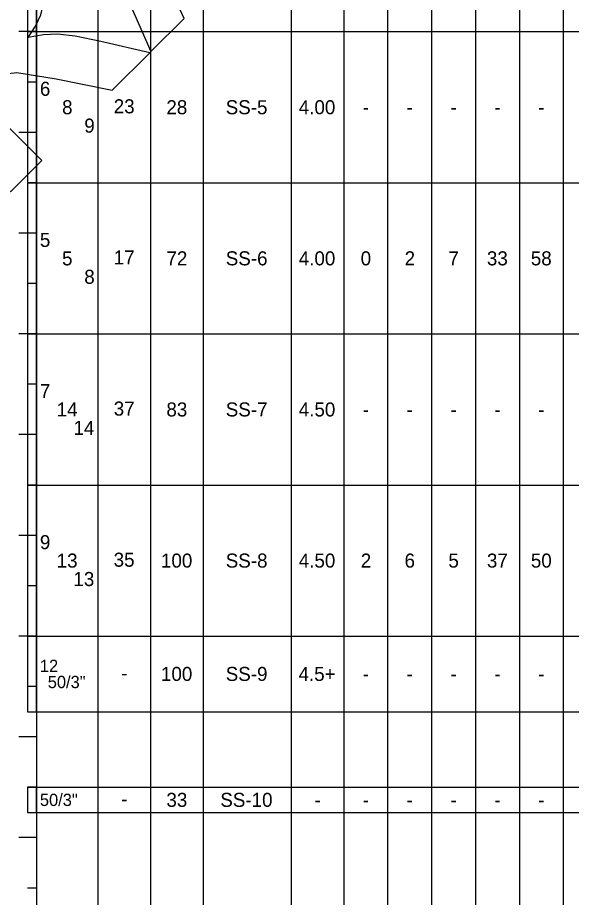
# Model space of a CAD drawing. Extents: x -0.01 to 0.83, y -0.63 to 1.27.
# Drawn here: x 0.4036 to 0.6664, y 0.45 to 0.8677 of the extents above; entities that cross this region are included whole.
import ezdxf

# ---------------------------------------------------------------- set-up
doc = ezdxf.new("R2010")
doc.units = 0

# ---------------------------------------------------------------- blocks, each defined once
blk = doc.blocks.new('DGRFC!DRAFT - ARIAL')
for points in [[(0, 0), (0.03155, 0), (0.03997, 0.00043), (0.04651, 0.00179), (0.05315, 0.00468), (0.05825, 0.00842), (0.06344, 0.01497), (0.06726, 0.02313), (0.06913, 0.03129), (0.06981, 0.0409), (0.06913, 0.05162), (0.06709, 0.06054), (0.06369, 0.06794), (0.05901, 0.07406), (0.05638, 0.07662), (0.05332, 0.07874), (0.05008, 0.08044), (0.0466, 0.08172), (0.03988, 0.08291), (0.03078, 0.08333), (0, 0.08333)], [(0.0841, 0), (0.10094, 0), (0.10094, 0.03478), (0.10434, 0.03478), (0.10935, 0.03452), (0.11275, 0.03376), (0.11539, 0.0324), (0.11786, 0.03036), (0.1267, 0.01811), (0.13878, 0), (0.15893, 0), (0.14872, 0.01616), (0.14337, 0.02449), (0.1392, 0.02976), (0.1352, 0.03333), (0.13027, 0.03673), (0.13537, 0.03776), (0.1398, 0.03946), (0.14354, 0.04167), (0.14668, 0.04439), (0.14906, 0.0477), (0.15085, 0.05136), (0.15187, 0.05544), (0.15221, 0.05986), (0.15128, 0.06692), (0.14847, 0.07313), (0.1466, 0.07577), (0.1443, 0.07798), (0.14175, 0.07968), (0.13878, 0.08104), (0.13537, 0.08206), (0.13095, 0.08274), (0.11947, 0.08333), (0.0841, 0.08333)], [(0.15952, 0), (0.1773, 0), (0.18427, 0.01896), (0.21752, 0.01896), (0.22474, 0), (0.24311, 0), (0.20978, 0.08333), (0.19192, 0.08333)], [(0.25204, 0), (0.26888, 0), (0.26888, 0.03546), (0.30349, 0.03546), (0.30349, 0.04949), (0.26888, 0.04949), (0.26888, 0.06922), (0.30901, 0.06922), (0.30901, 0.08333), (0.25204, 0.08333)], [(0.34167, 0), (0.3585, 0), (0.3585, 0.06922), (0.38308, 0.06922), (0.38308, 0.08333), (0.31701, 0.08333), (0.31701, 0.06922), (0.34167, 0.06922)], [(0.01684, 0.01412), (0.02942, 0.01412), (0.03954, 0.01488), (0.04328, 0.01616), (0.04634, 0.01828), (0.04881, 0.02151), (0.05077, 0.02636), (0.05213, 0.03291), (0.05247, 0.04167), (0.05213, 0.05017), (0.05085, 0.05646), (0.04872, 0.06105), (0.046, 0.06446), (0.04243, 0.06692), (0.03818, 0.06845), (0.03299, 0.06905), (0.0244, 0.06922), (0.01684, 0.06922)], [(0.10094, 0.04804), (0.11335, 0.04804), (0.12313, 0.0483), (0.1284, 0.04906), (0.13112, 0.05051), (0.13308, 0.05264), (0.13444, 0.05544), (0.13486, 0.05884), (0.13427, 0.06267), (0.13257, 0.06565), (0.12985, 0.06777), (0.12628, 0.06896), (0.11403, 0.06922), (0.10094, 0.06922)], [(0.18937, 0.03299), (0.21216, 0.03299), (0.20068, 0.06386)]]:
    blk.add_lwpolyline(points, close=True)

msp = doc.modelspace()

# ---------------------------------------------------------------- linework, layer by layer
for points in [[(0.4125, 1.22083), (0.4125, -0.62183)], [(0.4125, 1.22083), (0.4125, -0.62183)], [(0.44167, 1.22083), (0.44167, -0.62183)], [(0.46667, 1.22083), (0.46667, -0.62183)], [(0.49167, 1.22083), (0.49167, -0.62183)], [(0.53333, 1.22083), (0.53333, -0.62183)], [(0.55833, 1.22083), (0.55833, -0.62183)], [(0.6625, 1.22083), (0.6625, -0.62183)], [(0.57917, 1.20833), (0.57917, -0.62183)], [(0.6, 1.20833), (0.6, -0.62183)], [(0.62083, 1.20833), (0.62083, -0.62183)], [(0.64167, 1.20833), (0.64167, -0.62183)], [(0.40833, 0.93275), (0.40833, 0.861)], [(0.4125, 0.861), (0.40417, 0.861)], [(0.40833, 0.861), (0.4125, 0.861)], [(0.40833, 0.861), (0.40833, 0.78925)], [(0.40833, 0.861), (0.4125, 0.861)], [(0.4125, 0.861), (0.40833, 0.861)], [(0.4125, 0.861), (0.44167, 0.861)], [(0.44167, 0.861), (0.46667, 0.861)], [(0.46667, 0.861), (0.49167, 0.861)], [(0.49167, 0.861), (0.53333, 0.861)], [(0.53333, 0.861), (0.55833, 0.861)], [(0.55833, 0.861), (0.57917, 0.861)], [(0.57917, 0.861), (0.6, 0.861)], [(0.6, 0.861), (0.62083, 0.861)], [(0.62083, 0.861), (0.64167, 0.861)], [(0.64167, 0.861), (0.6625, 0.861)], [(0.6625, 0.861), (0.68333, 0.861)], [(0.4125, 0.83708), (0.40833, 0.83708)], [(0.4125, 0.81317), (0.40417, 0.81317)], [(0.4125, 0.81317), (0.40833, 0.81317)], [(0.40833, 0.78925), (0.4125, 0.78925)], [(0.40833, 0.78925), (0.40833, 0.7175)], [(0.40833, 0.78925), (0.4125, 0.78925)], [(0.4125, 0.78925), (0.40833, 0.78925)], [(0.4125, 0.78925), (0.44167, 0.78925)], [(0.44167, 0.78925), (0.46667, 0.78925)], [(0.46667, 0.78925), (0.49167, 0.78925)], [(0.49167, 0.78925), (0.53333, 0.78925)], [(0.53333, 0.78925), (0.55833, 0.78925)], [(0.55833, 0.78925), (0.57917, 0.78925)], [(0.57917, 0.78925), (0.6, 0.78925)], [(0.6, 0.78925), (0.62083, 0.78925)], [(0.62083, 0.78925), (0.64167, 0.78925)], [(0.64167, 0.78925), (0.6625, 0.78925)], [(0.6625, 0.78925), (0.68333, 0.78925)], [(0.4125, 0.76533), (0.40417, 0.76533)], [(0.4125, 0.76533), (0.40833, 0.76533)], [(0.4125, 0.74142), (0.40833, 0.74142)], [(0.4125, 0.7175), (0.40417, 0.7175)], [(0.40833, 0.7175), (0.4125, 0.7175)], [(0.40833, 0.7175), (0.40833, 0.64575)], [(0.40833, 0.7175), (0.4125, 0.7175)], [(0.4125, 0.7175), (0.40833, 0.7175)], [(0.4125, 0.7175), (0.44167, 0.7175)], [(0.44167, 0.7175), (0.46667, 0.7175)], [(0.46667, 0.7175), (0.49167, 0.7175)], [(0.49167, 0.7175), (0.53333, 0.7175)], [(0.53333, 0.7175), (0.55833, 0.7175)], [(0.55833, 0.7175), (0.57917, 0.7175)], [(0.57917, 0.7175), (0.6, 0.7175)], [(0.6, 0.7175), (0.62083, 0.7175)], [(0.62083, 0.7175), (0.64167, 0.7175)], [(0.64167, 0.7175), (0.6625, 0.7175)], [(0.6625, 0.7175), (0.68333, 0.7175)], [(0.4125, 0.69358), (0.40833, 0.69358)], [(0.4125, 0.66967), (0.40417, 0.66967)], [(0.4125, 0.66967), (0.40833, 0.66967)], [(0.40833, 0.64575), (0.4125, 0.64575)], [(0.40833, 0.64575), (0.40833, 0.574)], [(0.40833, 0.64575), (0.4125, 0.64575)], [(0.4125, 0.64575), (0.40833, 0.64575)], [(0.4125, 0.64575), (0.44167, 0.64575)], [(0.44167, 0.64575), (0.46667, 0.64575)], [(0.46667, 0.64575), (0.49167, 0.64575)], [(0.49167, 0.64575), (0.53333, 0.64575)], [(0.53333, 0.64575), (0.55833, 0.64575)], [(0.55833, 0.64575), (0.57917, 0.64575)], [(0.57917, 0.64575), (0.6, 0.64575)], [(0.6, 0.64575), (0.62083, 0.64575)], [(0.62083, 0.64575), (0.64167, 0.64575)], [(0.64167, 0.64575), (0.6625, 0.64575)], [(0.6625, 0.64575), (0.68333, 0.64575)], [(0.4125, 0.62183), (0.40417, 0.62183)], [(0.4125, 0.62183), (0.40833, 0.62183)], [(0.4125, 0.59792), (0.40833, 0.59792)], [(0.4125, 0.574), (0.40417, 0.574)], [(0.40833, 0.574), (0.4125, 0.574)], [(0.40833, 0.574), (0.40833, 0.53812)], [(0.40833, 0.574), (0.4125, 0.574)], [(0.4125, 0.574), (0.40833, 0.574)], [(0.4125, 0.574), (0.44167, 0.574)], [(0.44167, 0.574), (0.46667, 0.574)], [(0.46667, 0.574), (0.49167, 0.574)], [(0.49167, 0.574), (0.53333, 0.574)], [(0.53333, 0.574), (0.55833, 0.574)], [(0.55833, 0.574), (0.57917, 0.574)], [(0.57917, 0.574), (0.6, 0.574)], [(0.6, 0.574), (0.62083, 0.574)], [(0.62083, 0.574), (0.64167, 0.574)], [(0.64167, 0.574), (0.6625, 0.574)], [(0.6625, 0.574), (0.68333, 0.574)], [(0.4125, 0.55008), (0.40833, 0.55008)], [(0.40833, 0.53812), (0.4125, 0.53812)], [(0.4125, 0.53812), (0.44167, 0.53812)], [(0.44167, 0.53812), (0.46667, 0.53812)], [(0.46667, 0.53812), (0.49167, 0.53812)], [(0.49167, 0.53812), (0.53333, 0.53812)], [(0.53333, 0.53812), (0.55833, 0.53812)], [(0.55833, 0.53812), (0.57917, 0.53812)], [(0.57917, 0.53812), (0.6, 0.53812)], [(0.6, 0.53812), (0.62083, 0.53812)], [(0.62083, 0.53812), (0.64167, 0.53812)], [(0.64167, 0.53812), (0.6625, 0.53812)], [(0.6625, 0.53812), (0.68333, 0.53812)], [(0.4125, 0.52617), (0.40417, 0.52617)], [(0.4125, 0.52617), (0.40833, 0.52617)], [(0.40833, 0.50225), (0.40833, 0.49029)], [(0.40833, 0.50225), (0.4125, 0.50225)], [(0.4125, 0.50225), (0.40833, 0.50225)], [(0.4125, 0.50225), (0.44167, 0.50225)], [(0.44167, 0.50225), (0.46667, 0.50225)], [(0.46667, 0.50225), (0.49167, 0.50225)], [(0.49167, 0.50225), (0.53333, 0.50225)], [(0.53333, 0.50225), (0.55833, 0.50225)], [(0.55833, 0.50225), (0.57917, 0.50225)], [(0.57917, 0.50225), (0.6, 0.50225)], [(0.6, 0.50225), (0.62083, 0.50225)], [(0.62083, 0.50225), (0.64167, 0.50225)], [(0.64167, 0.50225), (0.6625, 0.50225)], [(0.6625, 0.50225), (0.68333, 0.50225)], [(0.40833, 0.49029), (0.4125, 0.49029)], [(0.4125, 0.49029), (0.44167, 0.49029)], [(0.44167, 0.49029), (0.46667, 0.49029)], [(0.46667, 0.49029), (0.49167, 0.49029)], [(0.49167, 0.49029), (0.53333, 0.49029)], [(0.53333, 0.49029), (0.55833, 0.49029)], [(0.55833, 0.49029), (0.57917, 0.49029)], [(0.57917, 0.49029), (0.6, 0.49029)], [(0.6, 0.49029), (0.62083, 0.49029)], [(0.62083, 0.49029), (0.64167, 0.49029)], [(0.64167, 0.49029), (0.6625, 0.49029)], [(0.6625, 0.49029), (0.68333, 0.49029)], [(0.4125, 0.47833), (0.40417, 0.47833)], [(0.4125, 0.47833), (0.40833, 0.47833)], [(0.4125, 0.45442), (0.40833, 0.45442)]]:
    msp.add_lwpolyline(points)
for points in [[(0.40833, 0.861), (0.4125, 0.861), (0.4125, 0.93275), (0.40833, 0.93275)], [(0.40833, 0.78925), (0.4125, 0.78925), (0.4125, 0.861), (0.40833, 0.861)], [(0.40833, 0.7175), (0.4125, 0.7175), (0.4125, 0.78925), (0.40833, 0.78925)], [(0.40833, 0.64575), (0.4125, 0.64575), (0.4125, 0.7175), (0.40833, 0.7175)], [(0.40833, 0.574), (0.4125, 0.574), (0.4125, 0.64575), (0.40833, 0.64575)], [(0.40833, 0.53812), (0.4125, 0.53812), (0.4125, 0.574), (0.40833, 0.574)], [(0.40833, 0.49029), (0.4125, 0.49029), (0.4125, 0.50225), (0.40833, 0.50225)]]:
    msp.add_lwpolyline(points, close=True)

# ---------------------------------------------------------------- block references
at = {"xscale": 1.25, "yscale": 1.25, "rotation": 45}
msp.add_blockref('DGRFC!DRAFT - ARIAL', (0.32586, 0.71054), dxfattribs=at)

# ---------------------------------------------------------------- texts
for s, height, p in [('6', 0.00667, (0.41417, 0.83054)), ('8', 0.00667, (0.4247, 0.82179)), ('23', 0.006667, (0.4492, 0.82221)), ('28', 0.006667, (0.47419, 0.82179)), ('SS-5', 0.006667, (0.50233, 0.82179)), ('4.00', 0.006667, (0.537, 0.82179)), ('-', 0.00667, (0.56734, 0.82179)), ('-', 0.00667, (0.58818, 0.82179)), ('-', 0.00667, (0.60901, 0.82179)), ('-', 0.00667, (0.62984, 0.82179)), ('-', 0.00667, (0.65068, 0.82179)), ('9', 0.00667, (0.43523, 0.81304)), ('5', 0.00667, (0.41417, 0.75879)), ('5', 0.00667, (0.42468, 0.75004)), ('17', 0.006667, (0.4492, 0.75046)), ('72', 0.006667, (0.47423, 0.75004)), ('SS-6', 0.006667, (0.50236, 0.75004)), ('4.00', 0.006667, (0.537, 0.75004)), ('0', 0.00667, (0.56638, 0.75004)), ('2', 0.00667, (0.58724, 0.75004)), ('7', 0.00667, (0.60804, 0.75004)), ('33', 0.006667, (0.62628, 0.75004)), ('58', 0.006667, (0.64711, 0.75004)), ('8', 0.00667, (0.43523, 0.74129)), ('7', 0.00667, (0.41417, 0.68704)), ('37', 0.006667, (0.4492, 0.67871)), ('83', 0.006667, (0.4742, 0.67829)), ('SS-7', 0.006667, (0.50236, 0.67829)), ('4.50', 0.006667, (0.537, 0.67829)), ('14', 0.006667, (0.42213, 0.67829)), ('-', 0.00667, (0.56734, 0.67829)), ('-', 0.00667, (0.58818, 0.67829)), ('-', 0.00667, (0.60901, 0.67829)), ('-', 0.00667, (0.62984, 0.67829)), ('-', 0.00667, (0.65068, 0.67829)), ('14', 0.006667, (0.4301, 0.66954)), ('9', 0.00667, (0.41417, 0.61529)), ('13', 0.006667, (0.42212, 0.60654)), ('35', 0.006667, (0.44917, 0.60696)), ('100', 0.006667, (0.47162, 0.60654)), ('SS-8', 0.006667, (0.50235, 0.60654)), ('4.50', 0.006667, (0.537, 0.60654)), ('2', 0.00667, (0.56641, 0.60654)), ('6', 0.00667, (0.5872, 0.60654)), ('5', 0.00667, (0.60801, 0.60654)), ('37', 0.006667, (0.62628, 0.60654)), ('50', 0.006667, (0.64713, 0.60654)), ('13', 0.006667, (0.43007, 0.59779)), ('12', 0.005833, (0.41417, 0.55697)), ('-', 0.00667, (0.45276, 0.55314)), ('100', 0.006667, (0.47162, 0.55273)), ('SS-9', 0.006667, (0.50235, 0.55273)), ('4.5+', 0.006667, (0.5369, 0.55273)), ('-', 0.00667, (0.56734, 0.55273)), ('-', 0.00667, (0.58818, 0.55273)), ('-', 0.00667, (0.60901, 0.55273)), ('-', 0.00667, (0.62984, 0.55273)), ('-', 0.00667, (0.65068, 0.55273)), ('50/3"', 0.005833, (0.4179, 0.54932)), ('50/3"', 0.005833, (0.41417, 0.49335)), ('33', 0.006667, (0.4742, 0.49294)), ('SS-10', 0.006667, (0.49978, 0.49294)), ('-', 0.00667, (0.45276, 0.49335)), ('-', 0.00667, (0.54443, 0.49294)), ('-', 0.00667, (0.56734, 0.49294)), ('-', 0.00667, (0.58818, 0.49294)), ('-', 0.00667, (0.60901, 0.49294)), ('-', 0.00667, (0.62984, 0.49294)), ('-', 0.00667, (0.65068, 0.49294))]:
    msp.add_text(s, height=height).set_placement(p)

doc.saveas('drawing.dxf')
